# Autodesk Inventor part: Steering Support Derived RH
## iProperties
Length Units: 11269
Angle Units: 11279
Time Units: 11290
Mass Units: 11283
Shininess: 3
Angle Display Precision: 2
Document Length Units: 11269
Document Angle Units: 11279
Document Time Units: 11290
Document Mass Units: 11283
Document Length Units Precision: 3
Document Angle Units Precision: 2
Compacted: True
Created: 2001-08
Part Number: Steering Support Derived RH
Document SubType Name: Modeling
Designer: Martin Budgell
Density: 0.0
Volumn: 0.0
Area: 0.0
PropertySet Name: Model Information
Control State: 0
Master: False
Checked Out: False
Author: Martin Budgell
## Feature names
1. Derived Body1 [Tagging]
